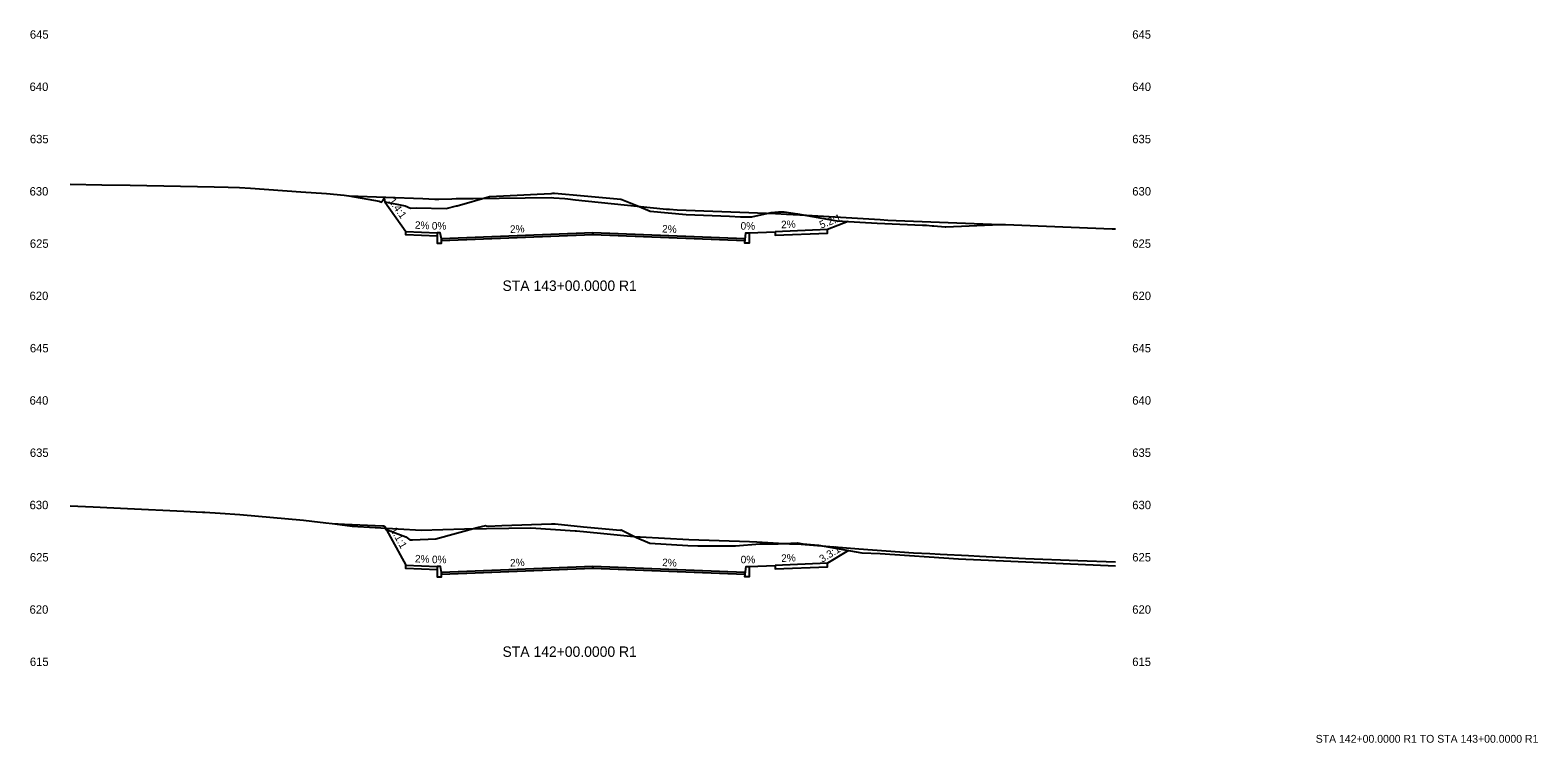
# Model space of a CAD drawing. Extents: x 12 to 301, y 16 to 1707.
# Drawn here: x 12.4 to 300.8, y 690.9 to 827.2 of the extents above; entities that cross this region are included whole.
import ezdxf

# ---------------------------------------------------------------- set-up
doc = ezdxf.new("R2010")
doc.units = 0
for name, color, linetype in [('BORD_text_large_2', 7, 'Continuous'), ('Default', 7, 'Continuous'), ('Draft_XS_Point_Label_Indicator', 7, 'Continuous'), ('Draft_XS_Text', 7, 'Continuous'), ('Grade_Veg_Grass', 7, 'Continuous'), ('P_XS_Sections', 7, 'Continuous'), ('Road_Curb', 7, 'Continuous'), ('Road_Pave_Asphalt', 7, 'Continuous'), ('Road_Sidewalk', 7, 'Continuous'), ('Terrain_Exterior', 7, 'Continuous')]:
    doc.layers.add(name, color=color, linetype=linetype)

msp = doc.modelspace()

# ---------------------------------------------------------------- linework, layer by layer
at = {"layer": 'Default'}
for points in [[(20, 797.75), (26.11, 797.63), (31.5, 797.57), (47.59, 797.29), (50.28, 797.21), (52.43, 797.14), (54.5, 797), (64.18, 796.33), (69.07, 796), (72.42, 795.65), (73.36, 795.55), (79.16, 794.5), (79.62, 794.33), (79.65, 794.39), (79.71, 794.46), (79.75, 794.52), (79.78, 794.56), (79.8, 794.6), (79.86, 794.67), (79.88, 794.7), (79.9, 794.73), (79.93, 794.77), (79.94, 794.78), (79.94, 794.79), (79.97, 794.83), (80, 794.87), (80, 794.87), (80, 794.87), (80, 794.88), (80.01, 794.89), (80.02, 794.9), (80.02, 794.9), (80.1, 795.25), (80.13, 795.12), (80.24, 794.37), (84.09, 793.61), (85.16, 793.19), (86.28, 793.24), (91.95, 793.1), (93.96, 793.65), (94.06, 793.64), (100.25, 795.44), (102.95, 795.53), (112.01, 796.01), (112.09, 796.01), (112.35, 796.05), (112.62, 796.02), (112.69, 796.02), (118.38, 795.54), (125.41, 794.93), (125.59, 794.85), (128.47, 793.7), (130.97, 792.61), (137.86, 791.94), (146.15, 791.65), (148.29, 791.52), (150.42, 791.53), (154.11, 792.35), (155.52, 792.46), (156.62, 792.51), (159.15, 792.07), (166.68, 790.73), (174.44, 790.32), (183.11, 789.95), (183.28, 789.94), (183.84, 789.9), (184.94, 789.82), (185.1, 789.81), (185.25, 789.8), (187.42, 789.64), (187.58, 789.63), (197.93, 790.03), (197.94, 790.03), (198.96, 790.04), (219.4, 789.24), (219.58, 789.23), (219.9, 789.22), (220, 789.21)], [(20, 736.23), (24.41, 736.05), (31.01, 735.73), (41.78, 735.2), (45.34, 735.03), (45.78, 735), (48.73, 734.82), (52.49, 734.6), (64.68, 733.48), (66.27, 733.33), (68.95, 733), (70.14, 732.85), (73.63, 732.69), (73.96, 732.67), (79.85, 732.4), (79.9, 732.4), (79.98, 732.4), (79.98, 732.4), (79.99, 732.4), (79.99, 732.4), (79.99, 732.4), (80.02, 732.4), (80.03, 732.4), (80.04, 732.4), (80.05, 732.42), (80.16, 732.29), (80.26, 732.26), (80.36, 731.8), (84.22, 730.31), (84.99, 729.72), (85.54, 729.72), (89.98, 729.91), (97.87, 732.07), (99.52, 732.45), (99.62, 732.43), (100.01, 732.38), (102.62, 732.47), (112.12, 732.79), (112.65, 732.78), (112.8, 732.78), (118.26, 732.2), (125.25, 731.59), (125.46, 731.65), (128.39, 730.19), (130.93, 729.1), (138.21, 728.66), (140.1, 728.57), (147.29, 728.58), (152, 728.98), (154.73, 728.98), (155.5, 728.98), (159.13, 729.14), (160.18, 728.94), (163.22, 728.71), (171.5, 727.24), (175.01, 727.15), (189.96, 726.08), (220, 724.77)]]:
    msp.add_lwpolyline(points, dxfattribs=at)
at = {"layer": 'Grade_Veg_Grass'}
for points in [[(80.24, 794.42), (80.24, 794.42), (84.24, 788.72)], [(168.9, 790.61), (168.9, 790.61), (164.9, 789.07)], [(149.9, 788.47), (154.9, 788.67)], [(80.26, 732.25), (80.26, 732.25), (84.26, 724.9)], [(168.93, 727.69), (168.93, 727.69), (164.93, 725.25)], [(149.93, 724.65), (154.93, 724.85)]]:
    msp.add_lwpolyline(points, dxfattribs=at)
at = {"layer": 'Road_Curb'}
for points in [[(90.24, 788.48), (90.24, 786.48), (91.07, 786.48), (91.07, 787.31), (90.84, 788.48), (90.24, 788.48)], [(149.9, 788.47), (149.9, 786.47), (149.07, 786.47), (149.3, 788.47), (149.9, 788.47)], [(90.26, 724.66), (90.26, 722.66), (91.1, 722.66), (91.1, 723.49), (90.87, 724.66), (90.26, 724.66)], [(149.93, 724.65), (149.93, 722.65), (149.1, 722.65), (149.33, 724.65), (149.93, 724.65)]]:
    msp.add_lwpolyline(points, dxfattribs=at)
at = {"layer": 'Road_Pave_Asphalt'}
for points in [[(120, 788.47), (91.07, 787.31), (91.07, 787.31), (91.07, 786.98), (120, 788.13), (120, 788.13), (120, 788.47), (120, 788.47), (120, 788.47)], [(120, 788.47), (120, 788.47), (120, 788.47), (120, 788.13), (120, 788.13), (149.07, 786.97), (149.07, 787.31), (149.07, 787.31), (120, 788.47)], [(120, 724.65), (91.1, 723.49), (91.1, 723.49), (91.1, 723.16), (120, 724.32), (120, 724.32), (120, 724.65), (120, 724.65), (120, 724.65)], [(120, 724.65), (120, 724.65), (120, 724.65), (120, 724.32), (120, 724.32), (149.1, 723.15), (149.1, 723.49), (149.1, 723.49), (120, 724.65)]]:
    msp.add_lwpolyline(points, dxfattribs=at)
at = {"layer": 'Road_Sidewalk'}
for points in [[(90.24, 788.48), (90.24, 787.81), (84.24, 788.05), (84.24, 788.72), (90.24, 788.48)], [(154.9, 788.67), (154.9, 788.01), (164.9, 788.41), (164.9, 789.07), (154.9, 788.67)], [(90.26, 724.66), (90.26, 723.99), (84.26, 724.23), (84.26, 724.9), (90.26, 724.66)], [(154.93, 724.85), (154.93, 724.19), (164.93, 724.59), (164.93, 725.25), (154.93, 724.85)]]:
    msp.add_lwpolyline(points, dxfattribs=at)
at = {"layer": 'Terrain_Exterior'}
for points in [[(20, 797.75), (26.11, 797.63), (31.5, 797.57), (47.59, 797.29), (50.28, 797.21), (52.43, 797.14), (54.5, 797), (64.18, 796.33), (69.07, 796), (72.42, 795.65), (73.36, 795.55), (87.49, 795), (89.79, 794.91), (90.54, 794.88), (93.05, 794.97), (93.88, 795), (94.3, 795.01), (97.14, 795.04), (112.02, 795.19), (112.54, 795.16), (114.64, 795), (115.23, 794.96), (116.7, 794.8), (133.5, 793.04), (134.04, 793), (134.67, 792.96), (136.16, 792.86), (154.97, 792.15), (157.1, 792.05), (160.89, 791.83), (175, 791), (176.45, 790.91), (178.03, 790.84), (197.93, 790.07), (198.96, 790.04), (219.4, 789.24), (219.58, 789.23), (219.9, 789.22), (220, 789.21)], [(20, 736.23), (24.41, 736.05), (31.01, 735.73), (41.78, 735.2), (45.34, 735.03), (45.78, 735), (48.73, 734.82), (52.49, 734.6), (64.68, 733.48), (66.27, 733.33), (68.95, 733), (70.14, 732.85), (73.96, 732.38), (87.21, 731.56), (95.44, 731.85), (108.14, 732.05), (116.63, 731.45), (116.92, 731.43), (121.47, 731), (128.52, 730.33), (129.07, 730.28), (138.39, 729.79), (150.01, 729.4), (151.37, 729.33), (157.66, 729), (159.87, 728.88), (170.94, 728), (181.35, 727.27), (184.51, 727.1), (186.48, 727), (191.87, 726.72), (194, 726.61), (202.82, 726.18), (212.81, 725.79), (220, 725.52)]]:
    msp.add_lwpolyline(points, dxfattribs=at)

# ---------------------------------------------------------------- texts
at = {"layer": 'BORD_text_large_2'}
msp.add_text('STA 142+00.0000 R1 TO STA 143+00.0000 R1', height=1.5, dxfattribs=at).set_placement((258.32, 690.92))
at = {"layer": 'Draft_XS_Point_Label_Indicator'}
for p in [(80.23, 794.41), (168.89, 790.6), (84.23, 788.71), (90.23, 788.47), (90.83, 788.47), (119.99, 788.46), (119.99, 788.46), (149.29, 788.46), (149.89, 788.46), (154.89, 788.66), (164.89, 789.06), (91.06, 787.3), (149.06, 787.29), (80.25, 732.24), (168.92, 727.68), (84.25, 724.89), (90.25, 724.65), (90.86, 724.65), (119.99, 724.64), (119.99, 724.64), (149.31, 724.64), (149.92, 724.64), (154.92, 724.84), (164.92, 725.24), (91.09, 723.48), (149.09, 723.47)]:
    msp.add_text('X', height=0.024, dxfattribs=at).set_placement(p)
at = {"layer": 'Draft_XS_Text'}
for s, height, p in [('645', 1.608, (12.32, 825.6)), ('645', 1.608, (223.22, 825.6)), ('640', 1.608, (12.26, 815.6)), ('640', 1.608, (223.22, 815.6)), ('635', 1.608, (12.32, 805.6)), ('635', 1.608, (223.22, 805.6)), ('630', 1.608, (12.26, 795.6)), ('630', 1.608, (223.22, 795.6)), ('625', 1.608, (12.32, 785.6)), ('625', 1.608, (223.22, 785.6)), ('STA 143+00.0000 R1', 1.992, (102.74, 777.35)), ('620', 1.608, (12.26, 775.6)), ('620', 1.608, (223.22, 775.6)), ('645', 1.608, (12.32, 765.6)), ('645', 1.608, (223.22, 765.6)), ('640', 1.608, (12.26, 755.6)), ('640', 1.608, (223.22, 755.6)), ('635', 1.608, (12.32, 745.6)), ('635', 1.608, (223.22, 745.6)), ('630', 1.608, (12.26, 735.6)), ('630', 1.608, (223.22, 735.6)), ('625', 1.608, (12.32, 725.6)), ('625', 1.608, (223.22, 725.6)), ('620', 1.608, (12.26, 715.6)), ('620', 1.608, (223.22, 715.6)), ('615', 1.608, (12.32, 705.6)), ('STA 142+00.0000 R1', 1.992, (102.74, 707.35)), ('615', 1.608, (223.22, 705.6))]:
    msp.add_text(s, height=height, dxfattribs=at).set_placement(p)
for s, rotation, p in [('1.4:1', 305.0328, (80.89, 794.53)), ('1.4:1', 305.0328, (80.89, 794.53)), ('1.4:1', 305.0328, (80.89, 794.53)), ('2%', 357.7094, (85.95, 789.25)), ('2%', 357.7094, (85.95, 789.25)), ('2%', 357.7094, (85.95, 789.25)), ('0%', 0, (89.22, 789.08)), ('0%', 0, (89.22, 789.08)), ('0%', 0, (89.22, 789.08)), ('0%', 0, (148.29, 789.07)), ('0%', 0, (148.29, 789.07)), ('0%', 0, (148.29, 789.07)), ('2%', 2.2906, (156.07, 789.32)), ('2%', 2.2906, (156.07, 789.32)), ('2%', 2.2906, (156.07, 789.32)), ('5.2:1', 21.0759, (163.7, 789.25)), ('5.2:1', 21.0759, (163.7, 789.25)), ('5.2:1', 21.0759, (163.7, 789.25)), ('2%', 2.2906, (104.2, 788.44)), ('2%', 2.2906, (104.2, 788.44)), ('2%', 2.2906, (104.2, 788.44)), ('2%', 357.7094, (133.25, 788.54)), ('2%', 357.7094, (133.25, 788.54)), ('2%', 357.7094, (133.25, 788.54)), ('1.1:1', 298.5658, (81.26, 731.67)), ('1.1:1', 298.5658, (81.26, 731.67)), ('1.1:1', 298.5658, (81.26, 731.67)), ('2%', 357.7094, (85.97, 725.43)), ('2%', 357.7094, (85.97, 725.43)), ('2%', 357.7094, (85.97, 725.43)), ('2%', 2.2906, (156.09, 725.5)), ('2%', 2.2906, (156.09, 725.5)), ('2%', 2.2906, (156.09, 725.5)), ('3.3:1', 31.3873, (163.89, 725.32)), ('3.3:1', 31.3873, (163.89, 725.32)), ('3.3:1', 31.3873, (163.89, 725.32)), ('0%', 0, (89.25, 725.26)), ('0%', 0, (89.25, 725.26)), ('0%', 0, (89.25, 725.26)), ('2%', 2.2906, (104.21, 724.62)), ('2%', 2.2906, (104.21, 724.62)), ('2%', 2.2906, (104.21, 724.62)), ('2%', 357.7094, (133.26, 724.72)), ('2%', 357.7094, (133.26, 724.72)), ('2%', 357.7094, (133.26, 724.72)), ('0%', 0, (148.31, 725.25)), ('0%', 0, (148.31, 725.25)), ('0%', 0, (148.31, 725.25))]:
    msp.add_text(s, height=1.44, rotation=rotation, dxfattribs=at).set_placement(p)
at = {"layer": 'P_XS_Sections'}
for p in [(20, 775), (20, 705)]:
    msp.add_text('-', height=0.0001, dxfattribs=at).set_placement(p)

doc.saveas('drawing.dxf')
